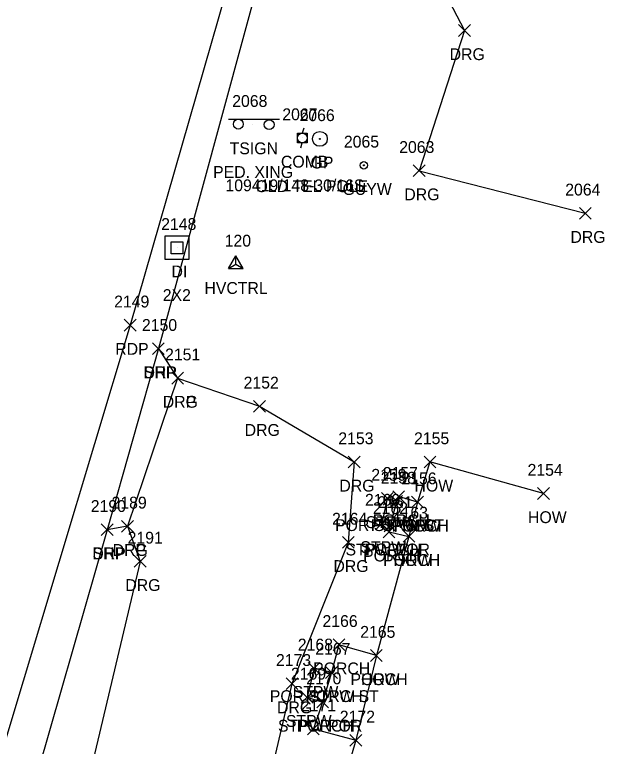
# Model space of a CAD drawing. Extents: x 1443071 to 1445292, y 614024 to 622563.
# Drawn here: x 1444655.5 to 1444755.2, y 622193 to 622316.6 of the extents above; entities that cross this region are included whole.
import ezdxf

# ---------------------------------------------------------------- set-up
doc = ezdxf.new("R2010")
doc.units = 0
for name, color, linetype in [('C_A', 7, 'Continuous'), ('C_I', 7, 'Continuous'), ('CPSM', 7, 'Continuous'), ('D_A', 7, 'Continuous'), ('D_C', 7, 'Continuous'), ('D_I', 7, 'Continuous'), ('DS', 7, 'Continuous'), ('L_A', 7, 'Continuous'), ('L_I', 7, 'Continuous'), ('L_TIC', 7, 'Continuous'), ('LBC', 7, 'Continuous'), ('LBF', 7, 'Continuous'), ('P_A', 7, 'Continuous'), ('P_I', 7, 'Continuous'), ('P_TIC', 7, 'Continuous'), ('PET', 7, 'Continuous'), ('PSP', 7, 'Continuous'), ('R_A', 7, 'Continuous'), ('R_C', 7, 'Continuous'), ('R_I', 7, 'Continuous'), ('R_TIC', 7, 'Continuous'), ('RDG', 7, 'Continuous'), ('RDP', 7, 'Continuous'), ('RGP', 7, 'Continuous'), ('S_A', 7, 'Continuous'), ('S_C', 7, 'Continuous'), ('S_I', 7, 'Continuous'), ('SSGN', 7, 'Continuous'), ('U_A', 7, 'Continuous'), ('U_C', 7, 'Continuous'), ('U_I', 7, 'Continuous'), ('UP', 7, 'Continuous'), ('UPGW', 7, 'Continuous')]:
    doc.layers.add(name, color=color, linetype=linetype)

msp = doc.modelspace()

# ---------------------------------------------------------------- linework, layer by layer
at = {"layer": 'CPSM'}
for p, q in [((1444691.61, 622273.7), (1444692.86, 622275.86)), ((1444694.11, 622273.7), (1444692.86, 622275.86)), ((1444692.86, 622274.42), (1444692.86, 622275.86)), ((1444691.61, 622273.7), (1444692.86, 622274.42)), ((1444692.86, 622274.42), (1444692.86, 622274.42)), ((1444692.86, 622274.42), (1444694.11, 622273.7)), ((1444691.61, 622273.7), (1444694.11, 622273.7))]:
    msp.add_line(p, q, dxfattribs=at)
at = {"layer": 'DS'}
for p, q in [((1444680.93, 622279.22), (1444684.93, 622279.22)), ((1444680.93, 622275.22), (1444680.93, 622279.22)), ((1444684.93, 622279.22), (1444684.93, 622275.22)), ((1444681.93, 622276.22), (1444681.93, 622278.22)), ((1444681.93, 622278.22), (1444683.93, 622278.22)), ((1444683.93, 622278.22), (1444683.93, 622276.22)), ((1444682.93, 622277.22), (1444682.93, 622277.22)), ((1444682.93, 622277.22), (1444682.93, 622277.22)), ((1444684.93, 622275.22), (1444680.93, 622275.22)), ((1444683.93, 622276.22), (1444681.93, 622276.22))]:
    msp.add_line(p, q, dxfattribs=at)
at = {"layer": 'L_TIC'}
for points in [[(1444724.69, 622240.03), (1444726.69, 622242.03)], [(1444726.69, 622240.03), (1444724.69, 622242.03)], [(1444717.47, 622233.85), (1444719.47, 622235.85)], [(1444719.47, 622233.85), (1444717.47, 622235.85)], [(1444719.39, 622234.17), (1444721.39, 622236.17)], [(1444721.39, 622234.17), (1444719.39, 622236.17)], [(1444743.88, 622234.69), (1444745.88, 622236.69)], [(1444745.88, 622234.69), (1444743.88, 622236.69)], [(1444719.05, 622233.35), (1444721.05, 622235.35)], [(1444721.05, 622233.35), (1444719.05, 622235.35)], [(1444719.05, 622233.35), (1444721.05, 622235.35)], [(1444721.05, 622233.35), (1444719.05, 622235.35)], [(1444722.59, 622233.25), (1444724.59, 622235.25)], [(1444724.59, 622233.25), (1444722.59, 622235.25)], [(1444722.59, 622233.25), (1444724.59, 622235.25)], [(1444724.59, 622233.25), (1444722.59, 622235.25)], [(1444716.52, 622229.63), (1444718.52, 622231.63)], [(1444718.52, 622229.63), (1444716.52, 622231.63)], [(1444717.97, 622229.23), (1444719.97, 622231.23)], [(1444719.97, 622229.23), (1444717.97, 622231.23)], [(1444717.97, 622229.23), (1444719.97, 622231.23)], [(1444719.97, 622229.23), (1444717.97, 622231.23)], [(1444717.76, 622228.21), (1444719.76, 622230.21)], [(1444719.76, 622228.21), (1444717.76, 622230.21)], [(1444721.14, 622227.45), (1444723.14, 622229.45)], [(1444723.14, 622227.45), (1444721.14, 622229.45)], [(1444721.14, 622227.45), (1444723.14, 622229.45)], [(1444723.14, 622227.45), (1444721.14, 622229.45)], [(1444709.3, 622209.14), (1444711.3, 622211.14)], [(1444711.3, 622209.14), (1444709.3, 622211.14)], [(1444715.63, 622207.31), (1444717.63, 622209.31)], [(1444717.63, 622207.31), (1444715.63, 622209.31)], [(1444715.63, 622207.31), (1444717.63, 622209.31)], [(1444717.63, 622207.31), (1444715.63, 622209.31)], [(1444705.08, 622205.16), (1444707.08, 622207.16)], [(1444707.08, 622205.16), (1444705.08, 622207.16)], [(1444708.03, 622204.45), (1444710.03, 622206.45)], [(1444710.03, 622204.45), (1444708.03, 622206.45)], [(1444708.03, 622204.45), (1444710.03, 622206.45)], [(1444710.03, 622204.45), (1444708.03, 622206.45)], [(1444703.93, 622200.25), (1444705.93, 622202.25)], [(1444705.93, 622200.25), (1444703.93, 622202.25)], [(1444706.54, 622199.45), (1444708.54, 622201.45)], [(1444708.54, 622199.45), (1444706.54, 622201.45)], [(1444706.54, 622199.45), (1444708.54, 622201.45)], [(1444708.54, 622199.45), (1444706.54, 622201.45)], [(1444704.98, 622194.91), (1444706.98, 622196.91)], [(1444706.98, 622194.91), (1444704.98, 622196.91)], [(1444712.14, 622192.99), (1444714.14, 622194.99)], [(1444714.14, 622192.99), (1444712.14, 622194.99)], [(1444712.14, 622192.99), (1444714.14, 622194.99)], [(1444714.14, 622192.99), (1444712.14, 622194.99)]]:
    msp.add_lwpolyline(points, dxfattribs=at)
at = {"layer": 'LBC'}
msp.add_lwpolyline([(1444744.88, 622235.69), (1444725.69, 622241.03), (1444723.59, 622234.25), (1444722.14, 622228.45), (1444716.63, 622208.31), (1444713.14, 622193.99), (1444706.72, 622171.79), (1444705.02, 622165.67), (1444698.9, 622145.01)], dxfattribs=at)
at = {"layer": 'LBF'}
for points in [[(1444720.05, 622234.35), (1444718.47, 622234.85), (1444717.52, 622230.63), (1444718.97, 622230.23)], [(1444723.59, 622234.25), (1444720.39, 622235.17), (1444720.05, 622234.35), (1444718.97, 622230.23), (1444718.76, 622229.21), (1444722.14, 622228.45)], [(1444716.63, 622208.31), (1444710.3, 622210.14), (1444709.03, 622205.45), (1444707.54, 622200.45), (1444705.98, 622195.91), (1444713.14, 622193.99)], [(1444709.03, 622205.45), (1444706.08, 622206.16), (1444704.93, 622201.25), (1444707.54, 622200.45)]]:
    msp.add_lwpolyline(points, dxfattribs=at)
at = {"layer": 'P_TIC'}
for points in [[(1444674, 622263.13), (1444676, 622265.13)], [(1444676, 622263.13), (1444674, 622265.13)], [(1444678.77, 622259.17), (1444680.77, 622261.17)], [(1444680.77, 622259.17), (1444678.77, 622261.17)], [(1444670.12, 622228.57), (1444672.12, 622230.57)], [(1444672.12, 622228.57), (1444670.12, 622230.57)]]:
    msp.add_lwpolyline(points, dxfattribs=at)
at = {"layer": 'PET'}
msp.add_lwpolyline([(1444754.44, 622544.13), (1444741.07, 622497.37), (1444724.21, 622436.63), (1444710.62, 622388.87), (1444697.45, 622342.15), (1444675, 622264.13), (1444650.85, 622183.92), (1444630.28, 622116), (1444610.88, 622049.25), (1444594.96, 621996.24), (1444563.37, 621884.27), (1444533.4, 621779.05), (1444495.09, 621640.86), (1444437.04, 621433.18), (1444409.83, 621332.84), (1444393.99, 621275.61), (1444360.23, 621155.32)], dxfattribs=at)
at = {"layer": 'PSP'}
msp.add_lwpolyline([(1444745.15, 622495.54), (1444738.65, 622472.69), (1444728.21, 622436.2), (1444714.89, 622387.13), (1444701.45, 622339.69), (1444679.77, 622260.17), (1444671.12, 622229.57), (1444657.52, 622182.26), (1444644.19, 622133.53), (1444626.95, 622072.43), (1444608.5, 622007.83), (1444599.1, 621977.5), (1444572.99, 621881.76), (1444551.74, 621805.05), (1444541.41, 621769.53), (1444519.46, 621688.51), (1444505.68, 621638.77), (1444452.32, 621450.13), (1444441.68, 621411.27), (1444418.22, 621330.76), (1444405.98, 621283.95), (1444397.04, 621252.99), (1444383.69, 621203.04)], dxfattribs=at)
at = {"layer": 'R_TIC'}
for points in [[(1444730.52, 622312.93), (1444732.52, 622314.93)], [(1444732.52, 622312.93), (1444730.52, 622314.93)], [(1444722.86, 622289.24), (1444724.86, 622291.24)], [(1444724.86, 622289.24), (1444722.86, 622291.24)], [(1444750.94, 622282.05), (1444752.94, 622284.05)], [(1444752.94, 622282.05), (1444750.94, 622284.05)], [(1444678.77, 622259.17), (1444680.77, 622261.17)], [(1444680.77, 622259.17), (1444678.77, 622261.17)], [(1444682.02, 622254.19), (1444684.02, 622256.19)], [(1444684.02, 622254.19), (1444682.02, 622256.19)], [(1444682.02, 622254.19), (1444684.02, 622256.19)], [(1444684.02, 622254.19), (1444682.02, 622256.19)], [(1444695.87, 622249.43), (1444697.87, 622251.43)], [(1444697.87, 622249.43), (1444695.87, 622251.43)], [(1444711.88, 622240.02), (1444713.88, 622242.02)], [(1444713.88, 622240.02), (1444711.88, 622242.02)], [(1444673.55, 622229.15), (1444675.55, 622231.15)], [(1444675.55, 622229.15), (1444673.55, 622231.15)], [(1444673.55, 622229.15), (1444675.55, 622231.15)], [(1444675.55, 622229.15), (1444673.55, 622231.15)], [(1444670.12, 622228.57), (1444672.12, 622230.57)], [(1444672.12, 622228.57), (1444670.12, 622230.57)], [(1444710.87, 622226.43), (1444712.87, 622228.43)], [(1444712.87, 622226.43), (1444710.87, 622228.43)], [(1444675.7, 622223.22), (1444677.7, 622225.22)], [(1444677.7, 622223.22), (1444675.7, 622225.22)], [(1444701.35, 622202.55), (1444703.35, 622204.55)], [(1444703.35, 622202.55), (1444701.35, 622204.55)]]:
    msp.add_lwpolyline(points, dxfattribs=at)
at = {"layer": 'RDG'}
for points in [[(1444701.45, 622339.69), (1444708.05, 622344.86), (1444717.19, 622341.36), (1444731.52, 622313.93), (1444723.86, 622290.24), (1444751.94, 622283.05)], [(1444683.02, 622255.19), (1444696.87, 622250.43), (1444712.88, 622241.02), (1444711.87, 622227.43), (1444702.35, 622203.55), (1444694.93, 622172.12), (1444687.86, 622144.11), (1444688.71, 622136.62), (1444696.22, 622134.93)], [(1444674.55, 622230.15), (1444676.7, 622224.22), (1444666.21, 622179.99), (1444651.88, 622133.47), (1444647.82, 622129.87)]]:
    msp.add_lwpolyline(points, dxfattribs=at)
at = {"layer": 'RDP'}
msp.add_lwpolyline([(1444679.77, 622260.17), (1444683.02, 622255.19), (1444674.55, 622230.15), (1444671.12, 622229.57)], dxfattribs=at)
at = {"layer": 'RGP'}
msp.add_line((1444707.07, 622295.62), (1444707.07, 622295.62), dxfattribs=at)
for radius in [1.25, 0.0833]:
    msp.add_circle((1444707.07, 622295.62), radius, dxfattribs=at)
at = {"layer": 'SSGN'}
for p, q in [((1444691.62, 622298.94), (1444700.22, 622298.94)), ((1444695.64, 622298.03), (1444695.64, 622298.03))]:
    msp.add_line(p, q, dxfattribs=at)
for centre in [(1444693.28, 622298.11), (1444698.5, 622298.03)]:
    msp.add_circle(centre, 0.833, dxfattribs=at)
at = {"layer": 'UP'}
for p, q in [((1444704.35, 622297.44), (1444704.1, 622296.6)), ((1444703.27, 622294.94), (1444703.27, 622296.6)), ((1444703.27, 622296.6), (1444704.93, 622296.6)), ((1444704.93, 622296.6), (1444704.93, 622294.94)), ((1444704.1, 622295.77), (1444704.1, 622295.77)), ((1444704.93, 622294.94), (1444703.27, 622294.94)), ((1444703.85, 622294.1), (1444704.1, 622294.94))]:
    msp.add_line(p, q, dxfattribs=at)
msp.add_circle((1444704.1, 622295.77), 0.833, dxfattribs=at)
at = {"layer": 'UPGW'}
for radius in [0.625, 0.0833]:
    msp.add_circle((1444714.51, 622291.15), radius, dxfattribs=at)

# ---------------------------------------------------------------- texts
at = {"layer": 'C_A'}
msp.add_text('HVCTRL', height=2, dxfattribs=at).set_placement((1444687.55, 622269.42))
at = {"layer": 'C_I'}
msp.add_text('120', height=2, dxfattribs=at).set_placement((1444690.98, 622277.42))
at = {"layer": 'D_A'}
msp.add_text('DI', height=2, dxfattribs=at).set_placement((1444681.99, 622272.22))
at = {"layer": 'D_C'}
msp.add_text('2X2', height=2, dxfattribs=at).set_placement((1444680.51, 622268.22))
at = {"layer": 'D_I'}
msp.add_text('2148', height=2, dxfattribs=at).set_placement((1444680.24, 622280.22))
at = {"layer": 'L_A'}
for s, p in [('HOW', (1444723.07, 622236.03)), ('PORCH', (1444716.02, 622230.17)), ('HOW', (1444742.26, 622230.69)), ('POR STPW ST', (1444709.64, 622229.35)), ('STPW', (1444714.86, 622229.85)), ('PORCH', (1444715.68, 622229.35)), ('PORCH', (1444719.22, 622229.25)), ('HOW', (1444720.98, 622229.25)), ('STPW POR', (1444711.42, 622225.23)), ('STPW', (1444713.92, 622225.63)), ('PORCH', (1444714.6, 622225.23)), ('PORCH', (1444714.38, 622224.21)), ('PORCH', (1444717.76, 622223.45)), ('HOW', (1444719.52, 622223.45)), ('PORCH', (1444705.93, 622205.14)), ('PORCH', (1444712.25, 622203.31)), ('HOW', (1444714.01, 622203.31)), ('POR STPW ST', (1444698.61, 622200.45)), ('STPW', (1444702.47, 622201.16)), ('PORCH', (1444704.65, 622200.45)), ('STPW POR', (1444699.99, 622195.45)), ('STPW', (1444701.33, 622196.25)), ('PORCH', (1444703.16, 622195.45))]:
    msp.add_text(s, height=2, dxfattribs=at).set_placement(p)
at = {"layer": 'L_I'}
for s, p in [('2155', (1444722.99, 622244.03)), ('2154', (1444742.18, 622238.69)), ('2159', (1444715.77, 622237.85)), ('2158', (1444717.36, 622237.35)), ('2158', (1444717.36, 622237.35)), ('2157', (1444717.7, 622238.17)), ('2156', (1444720.85, 622237.25)), ('2156', (1444720.85, 622237.25)), ('2160', (1444714.7, 622233.63)), ('2161', (1444716.8, 622233.23)), ('2161', (1444716.8, 622233.23)), ('2162', (1444716.02, 622232.21)), ('2163', (1444719.4, 622231.45)), ('2163', (1444719.4, 622231.45)), ('2166', (1444707.51, 622213.14)), ('2165', (1444713.89, 622211.31)), ('2165', (1444713.89, 622211.31)), ('2168', (1444703.34, 622209.16)), ('2167', (1444706.29, 622208.45)), ('2167', (1444706.29, 622208.45)), ('2169', (1444702.18, 622204.25)), ('2170', (1444704.76, 622203.45)), ('2170', (1444704.76, 622203.45)), ('2171', (1444703.86, 622198.91)), ('2172', (1444710.44, 622196.99)), ('2172', (1444710.44, 622196.99))]:
    msp.add_text(s, height=2, dxfattribs=at).set_placement(p)
at = {"layer": 'P_A'}
for s, p in [('RDP', (1444672.48, 622259.13)), ('SHP', (1444677.31, 622255.17)), ('SHP', (1444668.65, 622224.57))]:
    msp.add_text(s, height=2, dxfattribs=at).set_placement(p)
at = {"layer": 'P_I'}
for s, p in [('2149', (1444672.29, 622267.13)), ('2150', (1444676.99, 622263.17)), ('2190', (1444668.34, 622232.57))]:
    msp.add_text(s, height=2, dxfattribs=at).set_placement(p)
at = {"layer": 'R_A'}
for s, p in [('DRG', (1444729.01, 622308.93)), ('GP', (1444705.5, 622290.62)), ('DRG', (1444721.35, 622285.24)), ('DRG', (1444749.43, 622278.05)), ('DRP', (1444677.26, 622255.17)), ('DRG', (1444680.51, 622250.19)), ('DRP', (1444680.51, 622250.19)), ('DRG', (1444694.36, 622245.43)), ('DRG', (1444710.37, 622236.02)), ('DRG', (1444672.04, 622225.15)), ('DRP', (1444672.04, 622225.15)), ('DRP', (1444668.61, 622224.57)), ('DRG', (1444709.36, 622222.43)), ('DRG', (1444674.18, 622219.22)), ('DRG', (1444699.83, 622198.55))]:
    msp.add_text(s, height=2, dxfattribs=at).set_placement(p)
at = {"layer": 'R_C'}
msp.add_text('OLD TEL POLE', height=2, dxfattribs=at).set_placement((1444696.2, 622286.62))
at = {"layer": 'R_I'}
for s, p in [('2066', (1444703.63, 622298.62)), ('2063', (1444720.48, 622293.24)), ('2064', (1444748.55, 622286.05)), ('2150', (1444676.99, 622263.17)), ('2151', (1444680.9, 622258.19)), ('2151', (1444680.9, 622258.19)), ('2152', (1444694.18, 622253.43)), ('2153', (1444710.19, 622244.02)), ('2190', (1444668.34, 622232.57)), ('2189', (1444671.85, 622233.15)), ('2189', (1444671.85, 622233.15)), ('2164', (1444709.13, 622230.43)), ('2191', (1444674.57, 622227.22)), ('2173', (1444699.65, 622206.55))]:
    msp.add_text(s, height=2, dxfattribs=at).set_placement(p)
at = {"layer": 'S_A'}
msp.add_text('TSIGN', height=2, dxfattribs=at).set_placement((1444691.82, 622293.02))
at = {"layer": 'S_C'}
msp.add_text('PED. XING', height=2, dxfattribs=at).set_placement((1444689.02, 622289.02))
at = {"layer": 'S_I'}
msp.add_text('2068', height=2, dxfattribs=at).set_placement((1444692.25, 622301.02))
at = {"layer": 'U_A'}
for s, p in [('COMB', (1444700.49, 622290.77)), ('GUYW', (1444710.91, 622286.15))]:
    msp.add_text(s, height=2, dxfattribs=at).set_placement(p)
at = {"layer": 'U_C'}
msp.add_text('109419/148-30/16S', height=2, dxfattribs=at).set_placement((1444691.11, 622286.77))
at = {"layer": 'U_I'}
for s, p in [('2067', (1444700.72, 622298.77)), ('2065', (1444711.13, 622294.15))]:
    msp.add_text(s, height=2, dxfattribs=at).set_placement(p)

doc.saveas('drawing.dxf')
